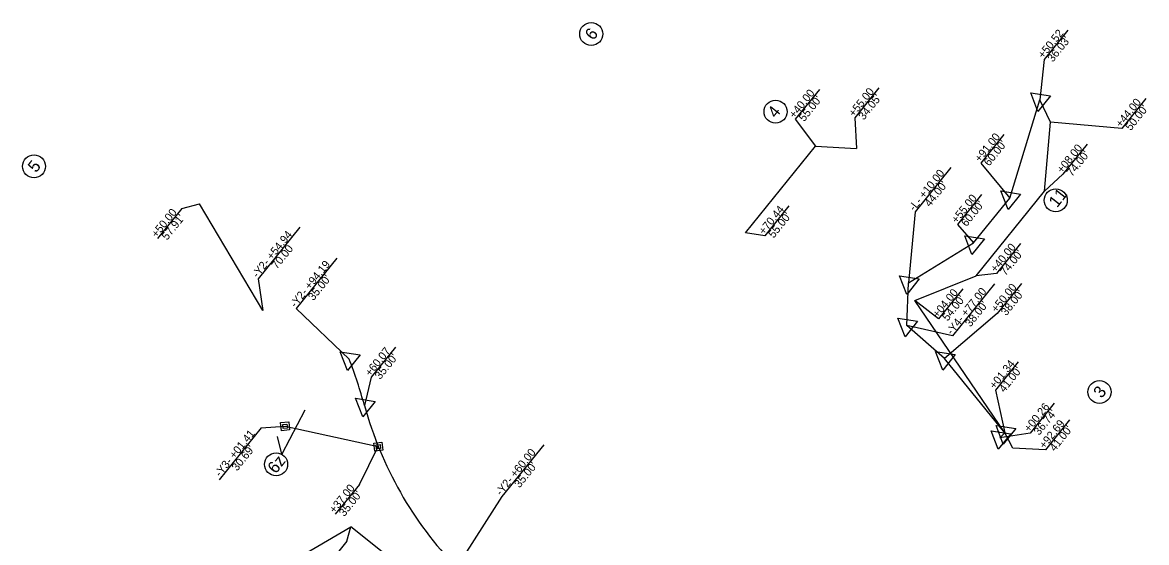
# Model space of a CAD drawing. Extents: x 1487704 to 1489071, y 498271 to 499440.
# Drawn here: x 1488369 to 1489071, y 499115 to 499440 of the extents above; entities that cross this region are included whole.
import ezdxf

# ---------------------------------------------------------------- set-up
doc = ezdxf.new("R2010")
doc.units = 0
for name, color, linetype in [('Prop Easement Construction', 7, 'Continuous'), ('Prop Easement Construction Station Offsets', 7, 'Continuous'), ('Prop Easement Permanent Drainage Station Offsets', 7, 'Continuous'), ('Prop ROW Marker CELL', 7, 'Continuous'), ('Prop ROW Permanent Easement CELL', 7, 'Continuous'), ('Prop ROW RW Lines', 7, 'Continuous'), ('Prop ROW Station Offsets', 7, 'Continuous'), ('Prop ROW Text', 7, 'Continuous')]:
    doc.layers.add(name, color=color, linetype=linetype)

msp = doc.modelspace()

# ---------------------------------------------------------------- linework, layer by layer
at = {"layer": 'Prop Easement Construction'}
for p, q in [((1489011.11, 499377.3), (1489004.32, 499391.14)), ((1489007.19, 499334.21), (1489011.11, 499377.3)), ((1488820.42, 499308.12), (1488864.09, 499362.26)), ((1488864.09, 499362.26), (1488889.81, 499360.78)), ((1488964.5, 499281.28), (1489007.19, 499334.21)), ((1488518.87, 499259.58), (1488479.18, 499326.25)), ((1488926.34, 499265.81), (1488964.5, 499281.28)), ((1488982.6, 499183.11), (1488926.34, 499265.81)), ((1488987.41, 499173.55), (1488982.6, 499183.13)), ((1488518.15, 499091.88), (1488573.75, 499124.4)), ((1488615.46, 499091.23), (1488573.75, 499124.4))]:
    msp.add_line(p, q, dxfattribs=at)
at = {"layer": 'Prop Easement Construction Station Offsets'}
for p, q in [((1488866.6, 499397.76), (1488851.5, 499379.04)), ((1488903.82, 499398.69), (1488888.72, 499379.98)), ((1489070.63, 499392.07), (1489055.54, 499373.35)), ((1489033.93, 499363.46), (1489018.83, 499344.75)), ((1488468.07, 499323.22), (1488452.97, 499304.5)), ((1488847.5, 499324.92), (1488832.44, 499306.26)), ((1488542.02, 499311.65), (1488515.83, 499279.28)), ((1488992.39, 499301.47), (1488977.3, 499282.75)), ((1488956.24, 499273.08), (1488941.14, 499254.36)), ((1489022.84, 499191.17), (1489007.82, 499172.55)), ((1488571.39, 499115.4), (1488545.91, 499083.92))]:
    msp.add_line(p, q, dxfattribs=at)
for points in [[(1488851.5, 499379.04), (1488864.09, 499362.26), (1488864.09, 499362.26)], [(1488888.72, 499379.98), (1488889.81, 499360.78)], [(1489055.54, 499373.35), (1489011.11, 499377.3), (1489011.11, 499377.3)], [(1489018.83, 499344.75), (1489007.19, 499334.21)], [(1488468.07, 499323.22), (1488479.18, 499326.25)], [(1488832.44, 499306.26), (1488820.42, 499308.12)], [(1488515.83, 499279.28), (1488518.87, 499259.58)], [(1488977.3, 499282.75), (1488964.5, 499281.28)], [(1488941.14, 499254.36), (1488926.34, 499265.81)], [(1489007.82, 499172.55), (1488987.41, 499173.55), (1488987.41, 499173.55)], [(1488571.39, 499115.4), (1488573.75, 499124.4)]]:
    msp.add_lwpolyline(points, dxfattribs=at)
at = {"layer": 'Prop Easement Permanent Drainage Station Offsets'}
for p, q in [((1488517.77, 499186.23), (1488532.73, 499187.23)), ((1488517.77, 499186.23), (1488491.54, 499153.81)), ((1488579.22, 499150.93), (1488564.1, 499132.23))]:
    msp.add_line(p, q, dxfattribs=at)
msp.add_lwpolyline([(1488579.22, 499150.93), (1488590.97, 499174.48)], dxfattribs=at)
at = {"layer": 'Prop ROW Marker CELL'}
for p, q in [((1489004.32, 499391.14), (1489004.32, 499391.14)), ((1488985.62, 499329.77), (1488985.62, 499329.77)), ((1488963.02, 499301.75), (1488963.02, 499301.75)), ((1488922.32, 499276.76), (1488922.32, 499276.76)), ((1488921.27, 499250.22), (1488921.27, 499250.22)), ((1488572.79, 499229.17), (1488572.79, 499229.17)), ((1488944.78, 499229.51), (1488944.78, 499229.51)), ((1488582.33, 499200.17), (1488582.33, 499200.17)), ((1488532.73, 499187.23), (1488532.73, 499187.23)), ((1488979.47, 499179.95), (1488979.47, 499179.95)), ((1488982.6, 499183.13), (1488982.6, 499183.13)), ((1488590.97, 499174.48), (1488590.97, 499174.48))]:
    msp.add_line(p, q, dxfattribs=at)
for points in [[(1489003.2, 499384.02), (1488998.72, 499395.66), (1489011.05, 499393.75)], [(1488984.5, 499322.64), (1488980.02, 499334.29), (1488992.35, 499332.37)], [(1488961.9, 499294.62), (1488957.42, 499306.27), (1488969.75, 499304.35)], [(1488921.2, 499269.64), (1488916.71, 499281.28), (1488929.04, 499279.37)], [(1488920.15, 499243.1), (1488915.67, 499254.74), (1488928, 499252.83)], [(1488571.67, 499222.05), (1488567.19, 499233.69), (1488579.52, 499231.78)], [(1488943.66, 499222.38), (1488939.18, 499234.03), (1488951.51, 499232.11)], [(1488581.21, 499193.04), (1488576.73, 499204.69), (1488589.06, 499202.77)], [(1488981.47, 499176.01), (1488976.99, 499187.65), (1488989.32, 499185.74)], [(1488978.35, 499172.83), (1488973.86, 499184.47), (1488986.19, 499182.56)]]:
    msp.add_lwpolyline(points, close=True, dxfattribs=at)
at = {"layer": 'Prop ROW Permanent Easement CELL'}
msp.add_line((1488532.73, 499187.23), (1488590.97, 499174.48), dxfattribs=at)
for points in [[(1488529.93, 499189.49), (1488534.99, 499190.03), (1488535.53, 499184.97), (1488530.47, 499184.43)], [(1488531.33, 499188.36), (1488533.86, 499188.63), (1488534.13, 499186.1), (1488531.6, 499185.83)], [(1488588.17, 499176.74), (1488593.23, 499177.29), (1488593.77, 499172.22), (1488588.71, 499171.68)], [(1488589.57, 499175.61), (1488592.1, 499175.89), (1488592.37, 499173.35), (1488589.84, 499173.08)]]:
    msp.add_lwpolyline(points, close=True, dxfattribs=at)
at = {"layer": 'Prop ROW RW Lines'}
for p, q in [((1488985.62, 499329.77), (1489004.32, 499391.14)), ((1488963.02, 499301.75), (1488985.62, 499329.77)), ((1488922.32, 499276.76), (1488963.02, 499301.75)), ((1488921.27, 499250.22), (1488922.32, 499276.76)), ((1488944.78, 499229.51), (1488921.27, 499250.22)), ((1488982.6, 499183.11), (1488944.78, 499229.51)), ((1488979.46, 499179.96), (1488982.6, 499183.13))]:
    msp.add_line(p, q, dxfattribs=at)
for centre, radius, start, end in [((1488292.94, 499121.08), 300, 15.2846, 21.11892), ((1488809.02, 499262.12), 235, 195.2846, 223.95368)]:
    msp.add_arc(centre, radius, start, end, dxfattribs=at)
at = {"layer": 'Prop ROW Station Offsets'}
for p, q in [((1489021.84, 499434.77), (1489006.99, 499416.35)), ((1488981.8, 499369.47), (1488967.46, 499351.68)), ((1488948.8, 499348.98), (1488926.36, 499321.15)), ((1488968.02, 499332.12), (1488952.93, 499313.4)), ((1488565.05, 499292.2), (1488539.65, 499260.81)), ((1488976.01, 499276.27), (1488949.83, 499243.81)), ((1488992.9, 499276.42), (1488977.8, 499257.7)), ((1488601.65, 499236.6), (1488586.5, 499217.87)), ((1488990.9, 499227.56), (1488976.6, 499209.82)), ((1489013.37, 499201.66), (1488998.34, 499183.01)), ((1488694.31, 499175.72), (1488668.08, 499143.3))]:
    msp.add_line(p, q, dxfattribs=at)
for points in [[(1489006.99, 499416.35), (1489004.32, 499391.14), (1489004.32, 499391.14)], [(1488967.46, 499351.68), (1488985.62, 499329.77)], [(1488926.36, 499321.15), (1488922.32, 499276.76), (1488922.32, 499276.76)], [(1488952.93, 499313.4), (1488963.02, 499301.75)], [(1488539.65, 499260.81), (1488572.79, 499229.17)], [(1488977.8, 499257.7), (1488944.78, 499229.51), (1488944.78, 499229.51)], [(1488949.83, 499243.81), (1488921.27, 499250.22), (1488921.27, 499250.22)], [(1488586.5, 499217.87), (1488582.33, 499200.17)], [(1488976.6, 499209.82), (1488982.6, 499183.13), (1488982.6, 499183.13)], [(1488998.34, 499183.01), (1488979.47, 499179.95), (1488979.46, 499179.96)], [(1488668.08, 499143.3), (1488639.84, 499099.01)]]:
    msp.add_lwpolyline(points, dxfattribs=at)
at = {"layer": 'Prop ROW Text'}
for p, q in [((1488724, 499432.36), (1488724, 499432.36)), ((1488839.2, 499383.82), (1488839.2, 499383.82)), ((1488375.79, 499349.66), (1488375.79, 499349.66)), ((1489014.31, 499328.41), (1489014.31, 499328.41)), ((1489041.65, 499208.64), (1489041.65, 499208.64)), ((1488544.94, 499197.25), (1488530.65, 499169.69)), ((1488530.65, 499169.69), (1488527.88, 499180.82)), ((1488527.11, 499163.43), (1488527.11, 499163.43))]:
    msp.add_line(p, q, dxfattribs=at)
for centre in [(1488724, 499432.36), (1488839.2, 499383.82), (1488375.79, 499349.66), (1489014.31, 499328.41), (1489041.65, 499208.64), (1488527.11, 499163.43)]:
    msp.add_circle(centre, 7.2, dxfattribs=at)

# ---------------------------------------------------------------- texts
at = {"layer": 'Prop Easement Construction Station Offsets'}
for s, rotation, p in [('+40.00', 51.11565, (1488851.02, 499379.24)), ('+55.00', 51.11565, (1488888.24, 499380.17)), ("55.00'", 51.11565, (1488857.13, 499377.25)), ("34.05'", 51.11565, (1488894.34, 499378.19)), ('+44.00', 51.11565, (1489055.05, 499373.55)), ("50.00'", 51.11565, (1489061.16, 499371.56)), ('+08.00', 51.11565, (1489018.35, 499344.94)), ("74.00'", 51.11565, (1489024.46, 499342.96)), ('+50.00', 51.11565, (1488452.49, 499304.7)), ('+70.44', 51.11565, (1488832.03, 499306.54)), ("55.00'", 51.11565, (1488838.05, 499304.44)), ("57.91'", 51.11565, (1488458.97, 499303.17)), ('-Y2- +54.94', 51.02567, (1488515.41, 499279.56)), ('70.00', 51.02567, (1488527.6, 499285.08)), ('+40.00', 51.11565, (1488976.82, 499282.95)), ("74.00'", 51.11565, (1488982.92, 499280.97)), ('+04.00', 51.11565, (1488940.66, 499254.56)), ("54.00'", 51.11565, (1488946.77, 499252.58)), ('+92.69', 51.11565, (1489007.33, 499172.73)), ("41.00'", 51.11565, (1489013.78, 499171.18))]:
    msp.add_text(s, height=5, rotation=rotation, dxfattribs=at).set_placement(p)
at = {"layer": 'Prop Easement Permanent Drainage Station Offsets'}
for s, p in [('-Y3- +01.41', (1488492.06, 499155.24)), ("30.69'", (1488502.71, 499158.87)), ('+37.00', (1488563.62, 499132.43)), ("35.00'", (1488569.72, 499130.44))]:
    msp.add_text(s, height=5, rotation=51.02567, dxfattribs=at).set_placement(p)
at = {"layer": 'Prop ROW Station Offsets'}
for s, rotation, p in [('+50.52', 51.11565, (1489006.55, 499416.62)), ("36.03'", 51.11565, (1489012.49, 499414.42)), ('+91.00', 51.11565, (1488966.98, 499351.88)), ("60.00'", 51.11565, (1488972.71, 499349.43)), ('-L- +10.00', 51.11565, (1488925.88, 499321.35)), ("44.00'", 51.11565, (1488935.66, 499323.92)), ('+55.00', 51.11565, (1488952.45, 499313.6)), ("60.00'", 51.11565, (1488958.55, 499311.61)), ('-Y2- +94.19', 51.02567, (1488539.16, 499260.99)), ("35.00'", 51.02567, (1488550.41, 499265.36)), ('-Y4- +77.00', 51.11565, (1488949.35, 499244.01)), ('+50.00', 51.11565, (1488977.32, 499257.9)), ("38.00'", 51.11565, (1488983.42, 499255.91)), ("38.00'", 51.11565, (1488960.99, 499248.89)), ('+60.07', 51.02567, (1488585.96, 499218)), ("35.00'", 51.02567, (1488592.13, 499216.09)), ('+01.34', 51.11565, (1488976.19, 499210.1)), ("41.00'", 51.11565, (1488982.2, 499208.01)), ('+00.26', 51.11565, (1488997.84, 499183.19)), ("36.74'", 51.11565, (1489003.93, 499181.19)), ('-Y2- +60.00', 51.02567, (1488667.6, 499143.5)), ("35.00'", 51.02567, (1488679.26, 499148.37))]:
    msp.add_text(s, height=5, rotation=rotation, dxfattribs=at).set_placement(p)
at = {"layer": 'Prop ROW Text'}
for s, p in [('6', (1488725.3, 499427.94)), ('4', (1488839.43, 499379.32)), ('5', (1488377.12, 499345.28)), ('11', (1489015.14, 499323.39)), ('3', (1489043.01, 499204.29)), ('6z', (1488526.93, 499157.12))]:
    msp.add_text(s, height=7.5, rotation=51.86672, dxfattribs=at).set_placement(p)

doc.saveas('drawing.dxf')
